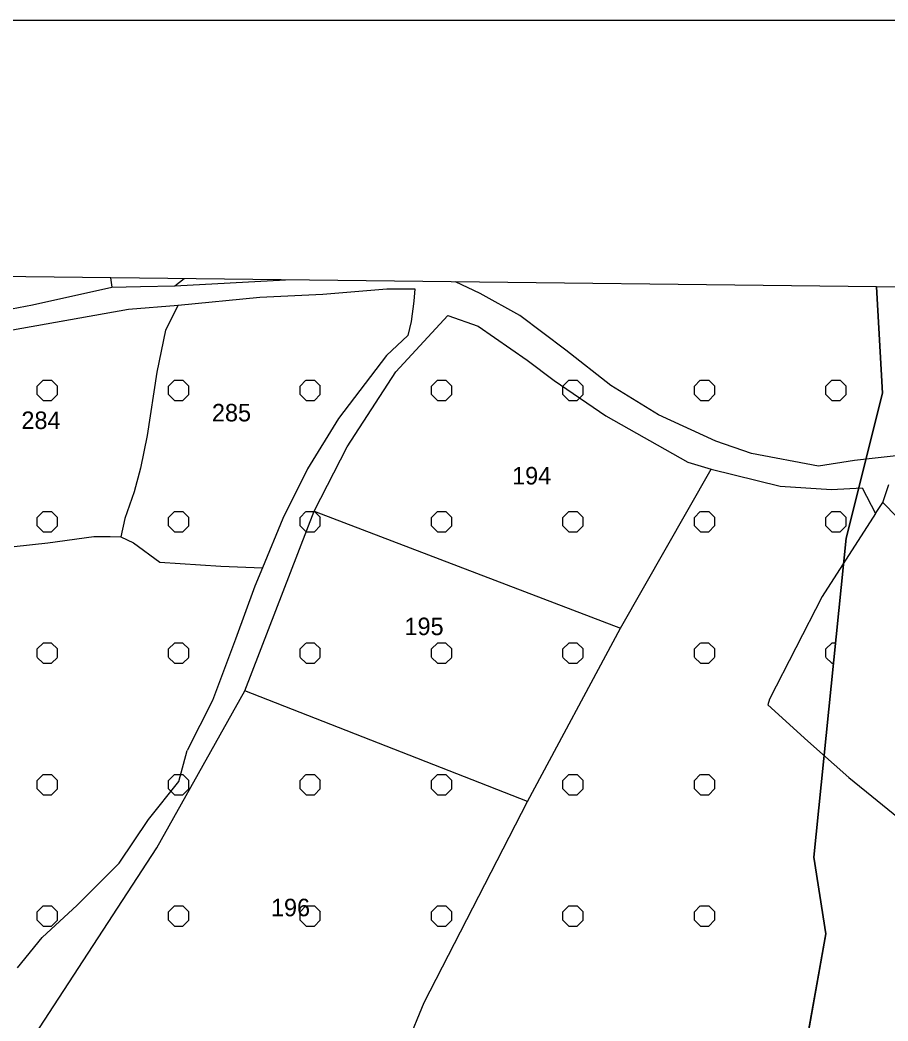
# Model space of a CAD drawing. Extents: x 410727 to 412947, y 4463506 to 4466382.
# Drawn here: x 411498.4 to 411696.5, y 4466153.2 to 4466381.6 of the extents above; entities that cross this region are included whole.
import ezdxf

# ---------------------------------------------------------------- set-up
doc = ezdxf.new("R2010")
doc.units = 0
for name, color, linetype in [('ADAKENARI', 7, 'Continuous'), ('KDS_PARSEL_NO', 7, 'Continuous'), ('KDS_PL', 7, 'Continuous'), ('LJ_ÇERÇEVE', 7, 'Continuous'), ('PL_KA_TARIM_DIGER', 7, 'Continuous'), ('PL_KA_TARIM_OZEL', 7, 'Continuous'), ('TR_OZELMAHSUL', 7, 'Continuous')]:
    doc.layers.add(name, color=color, linetype=linetype)

msp = doc.modelspace()

# ---------------------------------------------------------------- linework, layer by layer
at = {"layer": 'ADAKENARI'}
for p, q in [((411695.17, 4466296.47), (411693.82, 4466320.72)), ((411686.88, 4466263.31), (411695.17, 4466296.47)), ((411679.51, 4466190.55), (411686.88, 4466263.31)), ((411682.27, 4466173.05), (411679.51, 4466190.55)), ((411670.3, 4466105.81), (411682.27, 4466173.05))]:
    msp.add_line(p, q, dxfattribs=at)
at = {"layer": 'KDS_PL'}
for p, q in [((411519.03, 4466322.77), (411519.33, 4466320.64)), ((411533.71, 4466320.9), (411535.82, 4466322.57)), ((411501.25, 4466316.62), (411519.33, 4466320.64)), ((411519.33, 4466320.64), (411525.88, 4466320.77)), ((411525.88, 4466320.77), (411533.71, 4466320.9)), ((411533.71, 4466320.9), (411558.94, 4466322.3)), ((411567.48, 4466319.01), (411582.1, 4466320.26)), ((411582.1, 4466320.26), (411588.51, 4466320.26)), ((411588.51, 4466320.26), (411588.26, 4466317.44)), ((411603.41, 4466319.17), (411597.73, 4466321.85)), ((411534.47, 4466316.5), (411553.13, 4466318.31)), ((411553.13, 4466318.31), (411567.48, 4466319.01)), ((411612.44, 4466314.14), (411603.41, 4466319.17)), ((411481.43, 4466312.75), (411501.25, 4466316.62)), ((411523.13, 4466315.58), (411534.47, 4466316.5)), ((411534.47, 4466316.5), (411531.61, 4466310.84)), ((411588.26, 4466317.44), (411587.64, 4466312.78)), ((411480.92, 4466308.11), (411523.13, 4466315.58)), ((411584.12, 4466301.28), (411596.03, 4466314.19)), ((411596.03, 4466314.19), (411602.94, 4466311.72)), ((411622.93, 4466306.25), (411612.44, 4466314.14)), ((411587.64, 4466312.78), (411586.87, 4466309.57)), ((411602.94, 4466311.72), (411614.09, 4466304)), ((411531.61, 4466310.84), (411529.59, 4466301.22)), ((411586.87, 4466309.57), (411582, 4466305.04)), ((411582, 4466305.04), (411571.06, 4466290.62)), ((411633.24, 4466298.19), (411622.93, 4466306.25)), ((411614.09, 4466304), (411620.28, 4466299.31)), ((411529.59, 4466301.22), (411527.36, 4466286.8)), ((411573, 4466284.19), (411584.12, 4466301.28)), ((411620.28, 4466299.31), (411632.06, 4466291.25)), ((411644.1, 4466291.46), (411633.24, 4466298.19)), ((411571.06, 4466290.62), (411563.96, 4466279.19)), ((411632.06, 4466291.25), (411650.75, 4466280.72)), ((411657.2, 4466285.51), (411644.1, 4466291.46)), ((411527.36, 4466286.8), (411525.9, 4466279.35)), ((411565.47, 4466269.53), (411573, 4466284.19)), ((411665.3, 4466282.68), (411657.2, 4466285.51)), ((411680.58, 4466279.77), (411665.3, 4466282.68)), ((411704.34, 4466282.8), (411688.82, 4466281.1)), ((411525.9, 4466279.35), (411524.44, 4466273.91)), ((411563.96, 4466279.19), (411558.32, 4466267.84)), ((411650.75, 4466280.72), (411656.12, 4466279.12)), ((411688.82, 4466281.1), (411680.58, 4466279.77)), ((411635.38, 4466242.84), (411656.12, 4466279.12)), ((411656.12, 4466279.12), (411671.84, 4466275.19)), ((411671.84, 4466275.19), (411683.59, 4466274.44)), ((411683.59, 4466274.44), (411690.59, 4466274.81)), ((411690.59, 4466274.81), (411693.62, 4466268.94)), ((411695.25, 4466271.47), (411696.66, 4466275.56)), ((411524.44, 4466273.91), (411522.28, 4466267.85)), ((411693.62, 4466268.94), (411695.25, 4466271.47)), ((411695.25, 4466271.47), (411709.03, 4466257.31)), ((411522.28, 4466267.85), (411521.37, 4466263.67)), ((411549.66, 4466228.47), (411565.47, 4466269.53)), ((411558.32, 4466267.84), (411553.71, 4466256.59)), ((411565.47, 4466269.53), (411635.38, 4466242.84)), ((411693.62, 4466268.94), (411681.41, 4466250.03)), ((411504.7, 4466262.29), (411515.24, 4466263.76)), ((411515.24, 4466263.76), (411518.97, 4466263.76)), ((411518.97, 4466263.76), (411521.37, 4466263.67)), ((411521.37, 4466263.67), (411524.3, 4466262.28)), ((411497.04, 4466261.47), (411504.7, 4466262.29)), ((411524.3, 4466262.28), (411530.29, 4466257.89)), ((411530.29, 4466257.89), (411544.23, 4466256.93)), ((411544.23, 4466256.93), (411553.71, 4466256.59)), ((411553.71, 4466256.59), (411551.98, 4466252.38)), ((411551.98, 4466252.38), (411547.52, 4466240.26)), ((411681.41, 4466250.03), (411669.44, 4466226.62)), ((411614.22, 4466203.22), (411635.38, 4466242.84)), ((411547.52, 4466240.26), (411542.3, 4466226.33)), ((411529.62, 4466192.66), (411549.66, 4466228.47)), ((411614.22, 4466203.22), (411549.66, 4466228.47)), ((411669.44, 4466226.62), (411669, 4466225.28)), ((411542.3, 4466226.33), (411536.52, 4466214.91)), ((411669, 4466225.28), (411678.19, 4466217.04)), ((411678.19, 4466217.04), (411687.5, 4466208.69)), ((411534.63, 4466207.82), (411536.52, 4466214.91)), ((411687.5, 4466208.69), (411712.31, 4466188.59)), ((411527.66, 4466199.17), (411534.63, 4466207.82)), ((411590.62, 4466157.38), (411614.22, 4466203.22)), ((411521.03, 4466189.19), (411527.66, 4466199.17)), ((411501.66, 4466149.81), (411529.62, 4466192.66)), ((411511.4, 4466179.55), (411521.03, 4466189.19)), ((411503.43, 4466172.23), (411511.4, 4466179.55)), ((411497.79, 4466165.25), (411503.43, 4466172.23)), ((411574.94, 4466119.47), (411590.62, 4466157.38))]:
    msp.add_line(p, q, dxfattribs=at)
at = {"layer": 'LJ_ÇERÇEVE'}
msp.add_lwpolyline([(410732.32, 4466381.6), (412946.74, 4466381.6), (412946.74, 4463506.16), (410732.32, 4463506.16)], close=True, dxfattribs=at)
at = {"layer": 'PL_KA_TARIM_DIGER'}
msp.add_lwpolyline([(411836.34, 4466319.05), (411693.82, 4466320.72), (411695.17, 4466296.47), (411686.88, 4466263.31), (411679.51, 4466190.55), (411682.27, 4466173.05), (411670.3, 4466105.81)], dxfattribs=at)
at = {"layer": 'PL_KA_TARIM_OZEL'}
msp.add_lwpolyline([(411524.33, 4465912.08), (411524.97, 4465911.75), (411538.25, 4465904.8), (411538.25, 4465904.8), (411591.09, 4465931.74), (411635.3, 4465976.87), (411646.35, 4465988.84), (411652.8, 4466036.74), (411670.3, 4466088.31), (411670.3, 4466105.81), (411682.27, 4466173.05), (411679.51, 4466190.55), (411686.88, 4466263.31), (411695.17, 4466296.47), (411693.82, 4466320.72), (411344.35, 4466324.82)], dxfattribs=at)
at = {"layer": 'TR_OZELMAHSUL'}
for p, q in [((411502.28, 4466298.06), (411503.63, 4466299.41)), ((411502.29, 4466296.15), (411502.29, 4466298.07)), ((411503.64, 4466299.42), (411505.56, 4466299.42)), ((411506.92, 4466298.06), (411505.56, 4466299.41)), ((411506.91, 4466296.15), (411506.91, 4466298.07)), ((411532.28, 4466298.06), (411533.63, 4466299.41)), ((411532.29, 4466296.15), (411532.29, 4466298.07)), ((411533.64, 4466299.42), (411535.56, 4466299.42)), ((411536.92, 4466298.06), (411535.56, 4466299.41)), ((411536.91, 4466296.15), (411536.91, 4466298.07)), ((411562.28, 4466298.06), (411563.63, 4466299.41)), ((411562.29, 4466296.15), (411562.29, 4466298.07)), ((411563.64, 4466299.42), (411565.56, 4466299.42)), ((411566.92, 4466298.06), (411565.56, 4466299.41)), ((411566.91, 4466296.15), (411566.91, 4466298.07)), ((411592.27, 4466298.06), (411593.63, 4466299.41)), ((411592.29, 4466296.15), (411592.29, 4466298.07)), ((411593.64, 4466299.42), (411595.56, 4466299.42)), ((411596.92, 4466298.06), (411595.56, 4466299.41)), ((411596.91, 4466296.15), (411596.91, 4466298.07)), ((411622.27, 4466298.05), (411623.63, 4466299.41)), ((411622.29, 4466296.15), (411622.29, 4466298.07)), ((411623.64, 4466299.42), (411625.56, 4466299.42)), ((411626.92, 4466298.06), (411625.56, 4466299.41)), ((411626.91, 4466296.15), (411626.91, 4466298.07)), ((411652.27, 4466298.05), (411653.63, 4466299.41)), ((411652.29, 4466296.15), (411652.29, 4466298.07)), ((411653.64, 4466299.42), (411655.56, 4466299.42)), ((411656.92, 4466298.06), (411655.56, 4466299.41)), ((411656.91, 4466296.15), (411656.91, 4466298.07)), ((411682.27, 4466298.05), (411683.63, 4466299.41)), ((411682.29, 4466296.15), (411682.29, 4466298.07)), ((411683.64, 4466299.42), (411685.56, 4466299.42)), ((411686.92, 4466298.06), (411685.56, 4466299.41)), ((411686.91, 4466296.15), (411686.91, 4466298.07)), ((411503.65, 4466294.79), (411502.29, 4466296.14)), ((411505.55, 4466294.79), (411506.9, 4466296.14)), ((411533.65, 4466294.79), (411532.29, 4466296.14)), ((411535.55, 4466294.79), (411536.9, 4466296.14)), ((411563.65, 4466294.79), (411562.29, 4466296.14)), ((411565.55, 4466294.79), (411566.9, 4466296.14)), ((411593.65, 4466294.79), (411592.29, 4466296.14)), ((411595.54, 4466294.79), (411596.9, 4466296.14)), ((411623.65, 4466294.79), (411622.29, 4466296.14)), ((411625.54, 4466294.78), (411626.9, 4466296.14)), ((411653.65, 4466294.79), (411652.29, 4466296.14)), ((411655.54, 4466294.78), (411656.9, 4466296.14)), ((411683.65, 4466294.79), (411682.29, 4466296.14)), ((411685.54, 4466294.78), (411686.9, 4466296.14)), ((411503.64, 4466294.8), (411505.56, 4466294.8)), ((411533.64, 4466294.8), (411535.56, 4466294.8)), ((411563.64, 4466294.8), (411565.56, 4466294.8)), ((411593.64, 4466294.8), (411595.56, 4466294.8)), ((411623.64, 4466294.8), (411625.56, 4466294.8)), ((411653.64, 4466294.8), (411655.56, 4466294.8)), ((411683.64, 4466294.8), (411685.56, 4466294.8)), ((411502.28, 4466268.06), (411503.63, 4466269.41)), ((411502.29, 4466266.15), (411502.29, 4466268.07)), ((411503.64, 4466269.42), (411505.56, 4466269.42)), ((411506.92, 4466268.06), (411505.56, 4466269.41)), ((411506.91, 4466266.15), (411506.91, 4466268.07)), ((411532.28, 4466268.06), (411533.63, 4466269.41)), ((411532.29, 4466266.15), (411532.29, 4466268.07)), ((411533.64, 4466269.42), (411535.56, 4466269.42)), ((411536.92, 4466268.06), (411535.56, 4466269.41)), ((411536.91, 4466266.15), (411536.91, 4466268.07)), ((411562.28, 4466268.06), (411563.63, 4466269.41)), ((411562.29, 4466266.15), (411562.29, 4466268.07)), ((411563.64, 4466269.42), (411565.56, 4466269.42)), ((411566.92, 4466268.06), (411565.56, 4466269.41)), ((411566.91, 4466266.15), (411566.91, 4466268.07)), ((411592.27, 4466268.06), (411593.63, 4466269.41)), ((411592.29, 4466266.15), (411592.29, 4466268.07)), ((411593.64, 4466269.42), (411595.56, 4466269.42)), ((411596.92, 4466268.06), (411595.56, 4466269.41)), ((411596.91, 4466266.15), (411596.91, 4466268.07)), ((411622.27, 4466268.05), (411623.63, 4466269.41)), ((411622.29, 4466266.15), (411622.29, 4466268.07)), ((411623.64, 4466269.42), (411625.56, 4466269.42)), ((411626.92, 4466268.06), (411625.56, 4466269.41)), ((411626.91, 4466266.15), (411626.91, 4466268.07)), ((411652.27, 4466268.05), (411653.63, 4466269.41)), ((411652.29, 4466266.15), (411652.29, 4466268.07)), ((411653.64, 4466269.42), (411655.56, 4466269.42)), ((411656.92, 4466268.06), (411655.56, 4466269.41)), ((411656.91, 4466266.15), (411656.91, 4466268.07)), ((411682.27, 4466268.05), (411683.63, 4466269.41)), ((411682.29, 4466266.15), (411682.29, 4466268.07)), ((411683.64, 4466269.42), (411685.56, 4466269.42)), ((411686.92, 4466268.06), (411685.56, 4466269.41)), ((411686.91, 4466266.15), (411686.91, 4466268.07)), ((411503.65, 4466264.79), (411502.29, 4466266.14)), ((411505.55, 4466264.79), (411506.9, 4466266.14)), ((411533.65, 4466264.79), (411532.29, 4466266.14)), ((411535.55, 4466264.79), (411536.9, 4466266.14)), ((411563.65, 4466264.79), (411562.29, 4466266.14)), ((411565.55, 4466264.79), (411566.9, 4466266.14)), ((411593.65, 4466264.79), (411592.29, 4466266.14)), ((411595.54, 4466264.79), (411596.9, 4466266.14)), ((411623.65, 4466264.79), (411622.29, 4466266.14)), ((411625.54, 4466264.78), (411626.9, 4466266.14)), ((411653.65, 4466264.79), (411652.29, 4466266.14)), ((411655.54, 4466264.78), (411656.9, 4466266.14)), ((411683.65, 4466264.79), (411682.29, 4466266.14)), ((411685.54, 4466264.78), (411686.9, 4466266.14)), ((411503.64, 4466264.8), (411505.56, 4466264.8)), ((411533.64, 4466264.8), (411535.56, 4466264.8)), ((411563.64, 4466264.8), (411565.56, 4466264.8)), ((411593.64, 4466264.8), (411595.56, 4466264.8)), ((411623.64, 4466264.8), (411625.56, 4466264.8)), ((411653.64, 4466264.8), (411655.56, 4466264.8)), ((411683.64, 4466264.8), (411685.56, 4466264.8)), ((411502.28, 4466238.06), (411503.63, 4466239.41)), ((411502.29, 4466236.15), (411502.29, 4466238.07)), ((411503.64, 4466239.42), (411505.56, 4466239.42)), ((411506.92, 4466238.06), (411505.56, 4466239.41)), ((411506.91, 4466236.15), (411506.91, 4466238.07)), ((411532.28, 4466238.06), (411533.63, 4466239.41)), ((411532.29, 4466236.15), (411532.29, 4466238.07)), ((411533.64, 4466239.42), (411535.56, 4466239.42)), ((411536.92, 4466238.06), (411535.56, 4466239.41)), ((411536.91, 4466236.15), (411536.91, 4466238.07)), ((411562.28, 4466238.06), (411563.63, 4466239.41)), ((411562.29, 4466236.15), (411562.29, 4466238.07)), ((411563.64, 4466239.42), (411565.56, 4466239.42)), ((411566.92, 4466238.06), (411565.56, 4466239.41)), ((411566.91, 4466236.15), (411566.91, 4466238.07)), ((411592.27, 4466238.06), (411593.63, 4466239.41)), ((411592.29, 4466236.15), (411592.29, 4466238.07)), ((411593.64, 4466239.42), (411595.56, 4466239.42)), ((411596.92, 4466238.06), (411595.56, 4466239.41)), ((411596.91, 4466236.15), (411596.91, 4466238.07)), ((411622.27, 4466238.06), (411623.63, 4466239.41)), ((411622.29, 4466236.15), (411622.29, 4466238.07)), ((411623.64, 4466239.42), (411625.56, 4466239.42)), ((411626.92, 4466238.06), (411625.56, 4466239.41)), ((411626.91, 4466236.15), (411626.91, 4466238.07)), ((411652.27, 4466238.05), (411653.63, 4466239.41)), ((411652.29, 4466236.15), (411652.29, 4466238.07)), ((411653.64, 4466239.42), (411655.56, 4466239.42)), ((411656.92, 4466238.06), (411655.56, 4466239.41)), ((411656.91, 4466236.15), (411656.91, 4466238.07)), ((411682.27, 4466238.05), (411683.63, 4466239.41)), ((411682.29, 4466236.15), (411682.29, 4466238.07)), ((411683.64, 4466239.42), (411684.46, 4466239.42)), ((411503.65, 4466234.79), (411502.29, 4466236.14)), ((411505.55, 4466234.79), (411506.9, 4466236.14)), ((411533.65, 4466234.79), (411532.29, 4466236.14)), ((411535.55, 4466234.79), (411536.9, 4466236.14)), ((411563.65, 4466234.79), (411562.29, 4466236.14)), ((411565.55, 4466234.79), (411566.9, 4466236.14)), ((411593.65, 4466234.79), (411592.29, 4466236.14)), ((411595.54, 4466234.79), (411596.9, 4466236.14)), ((411623.65, 4466234.79), (411622.29, 4466236.14)), ((411625.54, 4466234.79), (411626.9, 4466236.14)), ((411653.65, 4466234.79), (411652.29, 4466236.14)), ((411655.54, 4466234.78), (411656.9, 4466236.14)), ((411683.65, 4466234.79), (411682.29, 4466236.14)), ((411503.64, 4466234.8), (411505.56, 4466234.8)), ((411533.64, 4466234.8), (411535.56, 4466234.8)), ((411563.64, 4466234.8), (411565.56, 4466234.8)), ((411593.64, 4466234.8), (411595.56, 4466234.8)), ((411623.64, 4466234.8), (411625.56, 4466234.8)), ((411653.64, 4466234.8), (411655.56, 4466234.8)), ((411683.64, 4466234.8), (411683.99, 4466234.8)), ((411502.28, 4466208.06), (411503.63, 4466209.41)), ((411503.64, 4466209.42), (411505.56, 4466209.42)), ((411506.92, 4466208.06), (411505.56, 4466209.41)), ((411532.28, 4466208.06), (411533.63, 4466209.41)), ((411533.64, 4466209.42), (411535.56, 4466209.42)), ((411536.92, 4466208.06), (411535.56, 4466209.41)), ((411562.28, 4466208.06), (411563.63, 4466209.41)), ((411563.64, 4466209.42), (411565.56, 4466209.42)), ((411566.92, 4466208.06), (411565.56, 4466209.41)), ((411592.27, 4466208.06), (411593.63, 4466209.41)), ((411593.64, 4466209.42), (411595.56, 4466209.42)), ((411596.92, 4466208.06), (411595.56, 4466209.41)), ((411622.27, 4466208.06), (411623.63, 4466209.41)), ((411623.64, 4466209.42), (411625.56, 4466209.42)), ((411626.92, 4466208.06), (411625.56, 4466209.41)), ((411652.27, 4466208.05), (411653.63, 4466209.41)), ((411653.64, 4466209.42), (411655.56, 4466209.42)), ((411656.91, 4466208.06), (411655.56, 4466209.41)), ((411502.29, 4466206.15), (411502.29, 4466208.07)), ((411503.65, 4466204.79), (411502.29, 4466206.14)), ((411505.55, 4466204.79), (411506.9, 4466206.14)), ((411506.91, 4466206.15), (411506.91, 4466208.07)), ((411532.29, 4466206.15), (411532.29, 4466208.07)), ((411533.65, 4466204.79), (411532.29, 4466206.14)), ((411535.55, 4466204.79), (411536.9, 4466206.14)), ((411536.91, 4466206.15), (411536.91, 4466208.07)), ((411562.29, 4466206.15), (411562.29, 4466208.07)), ((411563.65, 4466204.79), (411562.29, 4466206.14)), ((411565.55, 4466204.79), (411566.9, 4466206.14)), ((411566.91, 4466206.15), (411566.91, 4466208.07)), ((411592.29, 4466206.15), (411592.29, 4466208.07)), ((411593.65, 4466204.79), (411592.29, 4466206.14)), ((411595.54, 4466204.79), (411596.9, 4466206.14)), ((411596.91, 4466206.15), (411596.91, 4466208.07)), ((411622.29, 4466206.15), (411622.29, 4466208.07)), ((411623.65, 4466204.79), (411622.29, 4466206.14)), ((411625.54, 4466204.79), (411626.9, 4466206.14)), ((411626.91, 4466206.15), (411626.91, 4466208.07)), ((411652.29, 4466206.15), (411652.29, 4466208.07)), ((411653.64, 4466204.79), (411652.29, 4466206.14)), ((411655.54, 4466204.78), (411656.9, 4466206.14)), ((411656.91, 4466206.15), (411656.91, 4466208.07)), ((411503.64, 4466204.8), (411505.56, 4466204.8)), ((411533.64, 4466204.8), (411535.56, 4466204.8)), ((411563.64, 4466204.8), (411565.56, 4466204.8)), ((411593.64, 4466204.8), (411595.56, 4466204.8)), ((411623.64, 4466204.8), (411625.56, 4466204.8)), ((411653.64, 4466204.8), (411655.56, 4466204.8)), ((411502.28, 4466178.06), (411503.63, 4466179.41)), ((411503.64, 4466179.42), (411505.56, 4466179.42)), ((411506.92, 4466178.06), (411505.56, 4466179.41)), ((411532.28, 4466178.06), (411533.63, 4466179.41)), ((411533.64, 4466179.42), (411535.56, 4466179.42)), ((411536.92, 4466178.06), (411535.56, 4466179.41)), ((411562.28, 4466178.06), (411563.63, 4466179.41)), ((411563.64, 4466179.42), (411565.56, 4466179.42)), ((411566.92, 4466178.06), (411565.56, 4466179.41)), ((411592.27, 4466178.06), (411593.63, 4466179.41)), ((411593.64, 4466179.42), (411595.56, 4466179.42)), ((411596.91, 4466178.06), (411595.56, 4466179.41)), ((411622.27, 4466178.06), (411623.63, 4466179.41)), ((411623.64, 4466179.42), (411625.56, 4466179.42)), ((411626.91, 4466178.06), (411625.56, 4466179.41)), ((411652.27, 4466178.06), (411653.63, 4466179.41)), ((411653.64, 4466179.42), (411655.56, 4466179.42)), ((411656.91, 4466178.06), (411655.56, 4466179.41)), ((411502.29, 4466176.15), (411502.29, 4466178.07)), ((411506.91, 4466176.15), (411506.91, 4466178.07)), ((411532.29, 4466176.15), (411532.29, 4466178.07)), ((411536.91, 4466176.15), (411536.91, 4466178.07)), ((411562.29, 4466176.15), (411562.29, 4466178.07)), ((411566.91, 4466176.15), (411566.91, 4466178.07)), ((411592.29, 4466176.15), (411592.29, 4466178.07)), ((411596.91, 4466176.15), (411596.91, 4466178.07)), ((411622.29, 4466176.15), (411622.29, 4466178.07)), ((411626.91, 4466176.15), (411626.91, 4466178.07)), ((411652.29, 4466176.15), (411652.29, 4466178.07)), ((411656.91, 4466176.15), (411656.91, 4466178.07)), ((411503.65, 4466174.79), (411502.29, 4466176.14)), ((411503.64, 4466174.8), (411505.56, 4466174.8)), ((411505.55, 4466174.79), (411506.9, 4466176.14)), ((411533.65, 4466174.79), (411532.29, 4466176.14)), ((411533.64, 4466174.8), (411535.56, 4466174.8)), ((411535.55, 4466174.79), (411536.9, 4466176.14)), ((411563.65, 4466174.79), (411562.29, 4466176.14)), ((411563.64, 4466174.8), (411565.56, 4466174.8)), ((411565.55, 4466174.79), (411566.9, 4466176.14)), ((411593.64, 4466174.79), (411592.29, 4466176.14)), ((411593.64, 4466174.8), (411595.56, 4466174.8)), ((411595.54, 4466174.79), (411596.9, 4466176.14)), ((411623.64, 4466174.79), (411622.29, 4466176.14)), ((411623.64, 4466174.8), (411625.56, 4466174.8)), ((411625.54, 4466174.79), (411626.9, 4466176.14)), ((411653.64, 4466174.79), (411652.29, 4466176.14)), ((411653.64, 4466174.8), (411655.56, 4466174.8)), ((411655.54, 4466174.79), (411656.9, 4466176.14))]:
    msp.add_line(p, q, dxfattribs=at)

# ---------------------------------------------------------------- texts
at = {"layer": 'KDS_PARSEL_NO'}
for s, p in [('285', (411542.17, 4466289.99)), ('284', (411498.69, 4466288.25)), ('194', (411610.67, 4466275.6)), ('195', (411586.12, 4466241.21)), ('196', (411555.64, 4466177.05))]:
    msp.add_text(s, height=4, dxfattribs=at).set_placement(p)

doc.saveas('drawing.dxf')
